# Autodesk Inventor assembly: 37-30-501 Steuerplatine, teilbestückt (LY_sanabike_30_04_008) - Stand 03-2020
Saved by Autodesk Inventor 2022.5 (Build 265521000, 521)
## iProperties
Created: 2024-12
Part Number: 37-30-501 Steuerplatine, teilbestückt (LY_sanabike_30_04_008) - Stand 03-2020
Document SubType Name: Assembly
Designer: AdminForWorker
Title: 37-30-501 Steuerplatine, teilbestückt (LY_sanabike_30_04_008) - Stand 03-2020 v1
Author: AdminForWorker
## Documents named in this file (7)
- c:\worker\convert-fusion-r05-cosv3\tmp\job-1\131\temp\files\fda2321c-e64e-49b8-9f7e-d1d50770eb17\2abaf744-fe18-4e7d-9753-6a4ba5ed8b45.zip.iam
- c:\worker\convert-fusion-r05-cosv3\tmp\job-1\131\temp\files\fda2321c-e64e-49b8-9f7e-d1d50770eb17\Steuerplatine (LY_sanabike_30_04_008) - Stand 03-2020.ipt
- c:\worker\convert-fusion-r05-cosv3\tmp\job-1\131\temp\files\fda2321c-e64e-49b8-9f7e-d1d50770eb17\Stiftleiste 2-polig 90°gewinckelt - MTA-100 (TE connectivity 12162).ipt
- c:\worker\convert-fusion-r05-cosv3\tmp\job-1\131\temp\files\fda2321c-e64e-49b8-9f7e-d1d50770eb17\Steckerleiste SIL10x1 2,00mm.ipt
- c:\worker\convert-fusion-r05-cosv3\tmp\job-1\131\temp\files\fda2321c-e64e-49b8-9f7e-d1d50770eb17\Kragenstiftleiste 3x2 Pins (1761681-1).ipt
- c:\worker\convert-fusion-r05-cosv3\tmp\job-1\131\temp\files\fda2321c-e64e-49b8-9f7e-d1d50770eb17\Stiftwanne 13x2 Pins 90°.ipt
- c:\worker\convert-fusion-r05-cosv3\tmp\job-1\131\temp\files\fda2321c-e64e-49b8-9f7e-d1d50770eb17\SMD Taster 6x6mm.ipt
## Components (8 placed, 6 different names)
1. Steuerplatine (LY_sanabike_30_04_008) - Stand 03-2020:1
2. Stiftleiste 2-polig 90°gewinckelt - MTA-100 (TE connectivity 12162):1
3. Steckerleiste SIL10x1 2,00mm:1
4. Kragenstiftleiste 3x2 Pins (1761681-1):1
5. Stiftwanne 13x2 Pins 90°:1
6. SMD Taster 6x6mm:1
7. Stiftleiste 2-polig 90°gewinckelt - MTA-100 (TE connectivity 12162):2
8. Kragenstiftleiste 3x2 Pins (1761681-1):2
